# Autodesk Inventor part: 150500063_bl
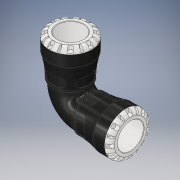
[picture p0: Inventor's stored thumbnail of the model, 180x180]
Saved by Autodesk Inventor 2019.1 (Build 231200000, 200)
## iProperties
Created: 2016-12
Part Number: 150500063_bl
Material: PVC-Piping
Description: PLASSON G-PLASS 90°  ELBOW 63X63
Document SubType Name: Modeling
Designer: KIM
Mass: 664.223 g
Surface Area: 733.008 cm^2
Volume: 474.445 cm^3
Density: 1.4 g/cm^3
Appearance: Black Cast
Author: KIM
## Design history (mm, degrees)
derived "150500.ipt"
feature "Solid1::150500.ipt" dims "ScaleForDerivedMember" = 10
tag "TaggingFeature1"
body "Solid1"
other parameters: "d1" = 39.9 [user parameter], "d2" = 63 [user parameter], "d3" = 78.75 [user parameter], "d4" = 103 [user parameter], "d8" = 87.55 [user parameter], "d13" = 9.7 [user parameter], "d14" = 9.7 [user parameter], "d15" = 0 [user parameter], "d17" = 360 deg [user parameter], "d19" = 8 deg [user parameter], "d20" = 1.26 [user parameter], "d21" = 1.26 [user parameter], "d22" = 8 deg [user parameter], "d24" = 0 [user parameter], "d26" = 360 deg [user parameter], "d33" = 10.3 [user parameter], "d43" = 80.34 [user parameter], "d51" = 1.03 [user parameter], "d54" = 22.05 [user parameter], "d55" = 13.86 [user parameter], "d57" = 19.012 [user parameter], "d58" = 0 [user parameter], "d74" = 0 [user parameter], "d77" = 5.25 [user parameter], "d78" = 95 [user parameter], "d82" = 1.26 [user parameter], "d115" = 360 deg [user parameter], "d207" = 90 deg [user parameter], "d228" = 18.7425 [user parameter], "d247" = 2.06 [user parameter], "d248" = 5.7 [user parameter], "d268" = 48.1525 [user parameter], "d269" = 5.7 [user parameter], "d270" = 146 [user parameter], "d272" = 90 deg [user parameter], "d274" = 0 [user parameter], "d275" = 0 [user parameter], "d_" = 63 [user parameter], "E_" = 103 [user parameter], "l_" = 95 [user parameter], "A_" = 146 [user parameter], "d9" = 12.125 [user parameter], "d11" = 103 [user parameter], "d12" = 78.75 [user parameter]
